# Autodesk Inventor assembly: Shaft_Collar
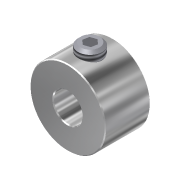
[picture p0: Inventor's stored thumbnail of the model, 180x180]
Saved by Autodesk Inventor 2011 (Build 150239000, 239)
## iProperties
Created: 2008-03
Part Number: Shaft_Collar
Document SubType Name: Assembly
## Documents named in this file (3)
- C:\Data Folder\VEX 2011\Inventor Datasets\Unit 9\Components\Shaft_Collar.iam
- C:\Data Folder\VEX 2011\Inventor Datasets\Unit 9\Components\SHAFT-COLLAR.ipt
- C:\Data Folder\VEX 2011\Inventor Datasets\Unit 9\Content Center\en-US\ANSI B18.3(08)\ANSI B18.3 - 6-40 UNF - 0.188(24).ipt
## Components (2 placed, 2 different names)
1. SHAFT-COLLAR:1 — Mate:2
2. Hexagon Socket Set Screw - Flat Point - Inch 6-40 UNF x 0.188:2 — Mate:2, Flush:2
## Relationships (2: Mate 1, Flush 1)
- Mate:2: SHAFT-COLLAR:1 ↔ Hexagon Socket Set Screw - Flat Point - Inch 6-40 UNF x 0.188:2
- Flush:2: Hexagon Socket Set Screw - Flat Point - Inch 6-40 UNF x 0.188:2
